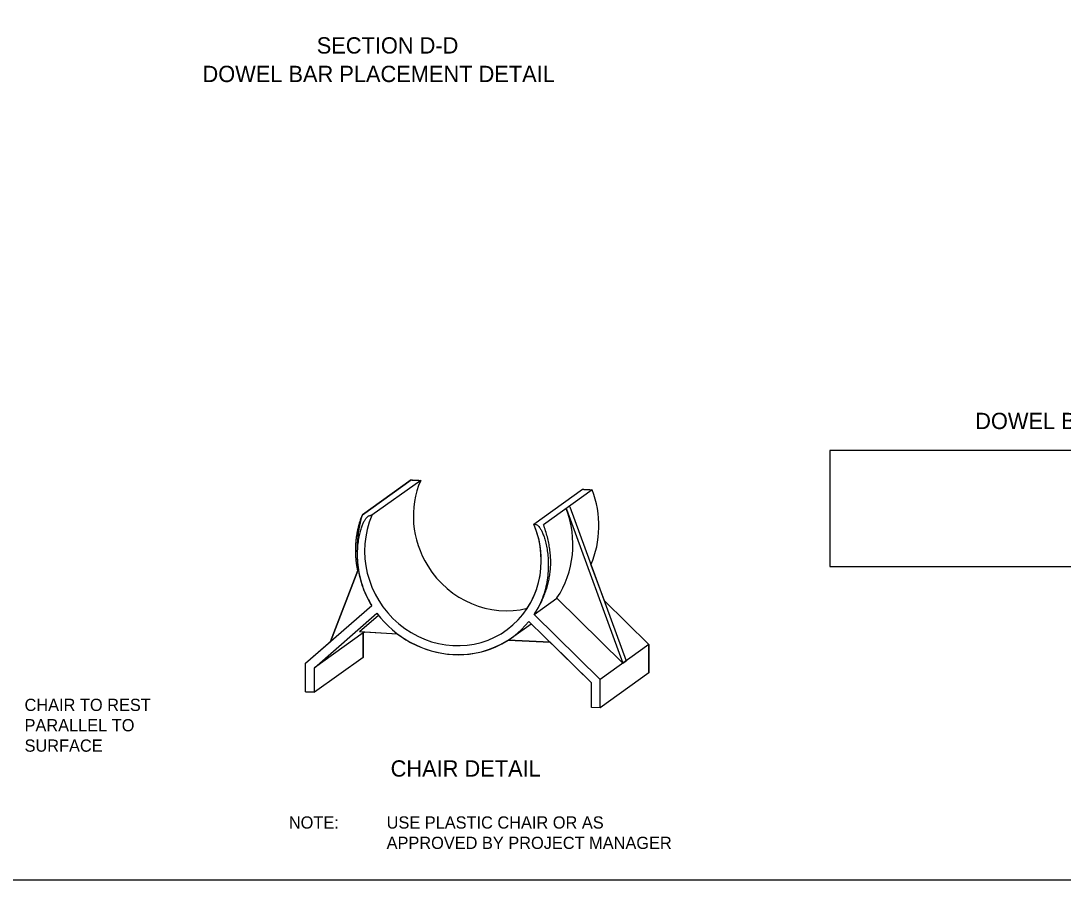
# Model space of a CAD drawing. Extents: x 49991.4 to 50021, y 49987.6 to 50011.4.
# Drawn here: x 50005.98 to 50011.1, y 49987.8 to 49992.02 of the extents above; entities that cross this region are included whole.
import ezdxf

# ---------------------------------------------------------------- set-up
doc = ezdxf.new("R2010")
doc.units = 0
for name, color, linetype in [('Level 1', 7, 'Continuous'), ('Level 15', 7, 'Continuous'), ('Level 16', 7, 'Continuous'), ('Level 2', 7, 'Continuous')]:
    doc.layers.add(name, color=color, linetype=linetype)

msp = doc.modelspace()

# ---------------------------------------------------------------- linework, layer by layer
at = {"layer": 'Level 1'}
for p, q in [((50007.9466, 49989.7609), (50007.7071, 49989.5897)), ((50008.7886, 49989.715), (50008.5492, 49989.5438)), ((50008.6624, 49989.6197), (50008.9394, 49988.8643)), ((50008.6784, 49989.6312), (50008.9554, 49988.8757)), ((50008.5032, 49989.103), (50008.615, 49989.1829)), ((50008.9394, 49988.8643), (50008.615, 49989.1829)), ((50007.3817, 49988.8632), (50007.7062, 49989.1464)), ((50007.4251, 49988.8413), (50007.7318, 49989.1091)), ((50007.7399, 49989.0986), (50007.6468, 49989.0172)), ((50008.3926, 49988.9889), (50008.4887, 49989.0576)), ((50008.7843, 49988.7673), (50008.4776, 49989.0685)), ((50008.8277, 49988.7844), (50008.5032, 49989.103)), ((50007.6646, 49989.0126), (50007.4251, 49988.8413)), ((50007.8335, 49989.007), (50007.6468, 49989.0172)), ((50009.0671, 49988.9556), (50008.8277, 49988.7844)), ((50007.4251, 49988.721), (50007.4251, 49988.8413)), ((50008.8277, 49988.6446), (50008.8277, 49988.7844))]:
    msp.add_line(p, q, dxfattribs=at)
msp.add_lwpolyline([(49999.3835, 49998.9992), (50016.7501, 49998.9992), (50016.7501, 49987.7988), (49999.3835, 49987.7988)], close=True, dxfattribs=at)
for points in [[(50007.6602, 49989.5922), (50007.8997, 49989.7634)], [(50008.5023, 49989.5464), (50008.7417, 49989.7176)], [(50007.8335, 49989.007), (50007.6685, 49989.016), (50007.6646, 49989.0126), (50007.6646, 49988.8922), (50007.4251, 49988.721), (50007.3817, 49988.7234), (50007.3817, 49988.8632), (50007.5036, 49988.9696), (50007.6373, 49989.3195)], [(50008.7825, 49989.3472), (50008.8467, 49989.1721), (50009.0671, 49988.9556), (50009.0671, 49988.8158), (50008.8277, 49988.6446), (50008.7843, 49988.647), (50008.7843, 49988.7673), (50008.5816, 49988.9663), (50008.3759, 49988.9775)]]:
    msp.add_lwpolyline(points, dxfattribs=at)
for centre, major_axis, start_param, end_param in [((50008.3441, 49989.5628), (0.2617, -0.366), 3.653116, 4.644013), ((50008.3441, 49989.5628), (0.2879, -0.4027), 0.51692, 1.295209), ((50008.2164, 49989.4715), (-0.2879, 0.4027), 3.485253, 4.436802), ((50008.1047, 49989.3916), (-0.2617, 0.366), 0.511524, 4.47615), ((50008.1047, 49989.3916), (-0.2617, 0.366), 3.495016, 4.47615), ((50008.3441, 49989.5628), (0.2617, -0.366), 4.644013, 5.929762), ((50008.1047, 49989.3916), (-0.2879, 0.4027), 1.596779, 3.390895), ((50008.1047, 49989.3916), (-0.2879, 0.4027), 1.88936, 3.098314)]:
    msp.add_ellipse(centre, major_axis=major_axis, ratio=0.944998, start_param=start_param, end_param=end_param, dxfattribs=at)
for points, degree in [([(50007.8997, 49989.7634), (50007.9231, 49989.7622), (50007.9466, 49989.7609)], 2), ([(50008.7417, 49989.7176), (50008.7652, 49989.7163), (50008.7886, 49989.715)], 2), ([(50007.6297, 49989.4632), (50007.6359, 49989.5304), (50007.6602, 49989.5922)], 2), ([(50007.7062, 49989.1464), (50007.5705, 49989.3634), (50007.6602, 49989.5922), (50007.6837, 49989.5909), (50007.7071, 49989.5897)], 4), ([(50008.5023, 49989.5464), (50008.5257, 49989.5451), (50008.5492, 49989.5438), (50008.6389, 49989.3052), (50008.5032, 49989.103)], 4), ([(50007.6373, 49989.3195), (50007.6229, 49989.3914), (50007.6297, 49989.4632)], 2)]:
    msp.add_open_spline(points, degree=degree, dxfattribs=at)
at = {"layer": 'Level 15'}
msp.add_line((50008.9394, 49988.8643), (50008.9554, 49988.8757), dxfattribs=at)
at = {"layer": 'Level 16'}
for p, q in [((50007.8997, 49989.7634), (50007.6602, 49989.5922)), ((50008.5023, 49989.5464), (50008.7417, 49989.7176)), ((50007.6373, 49989.3195), (50007.5036, 49988.9696)), ((50009.0671, 49988.9556), (50008.8467, 49989.1721)), ((50007.6646, 49989.0126), (50007.6685, 49989.016)), ((50007.6646, 49988.8922), (50007.6646, 49989.0126)), ((50008.3759, 49988.9775), (50008.5816, 49988.9663)), ((50009.0671, 49988.8158), (50009.0671, 49988.9556)), ((50007.3817, 49988.7234), (50007.3817, 49988.8632)), ((50007.6646, 49988.8922), (50007.4251, 49988.721)), ((50009.0671, 49988.8158), (50008.8277, 49988.6446)), ((50008.7843, 49988.647), (50008.7843, 49988.7673)), ((50007.3817, 49988.7234), (50007.4251, 49988.721)), ((50008.8277, 49988.6446), (50008.7843, 49988.647))]:
    msp.add_line(p, q, dxfattribs=at)
for centre, major_axis, start_param, end_param in [((50008.3441, 49989.5628), (0.2617, -0.366), 3.653116, 4.644013), ((50008.3441, 49989.5628), (0.2879, -0.4027), 0.51692, 1.295209), ((50008.2324, 49989.4829), (-0.2879, 0.4027), 4.428217, 4.436802), ((50008.3441, 49989.5628), (0.2617, -0.366), 4.644013, 5.929762), ((50008.2164, 49989.4715), (-0.2879, 0.4027), 3.482403, 3.485253)]:
    msp.add_ellipse(centre, major_axis=major_axis, ratio=0.944998, start_param=start_param, end_param=end_param, dxfattribs=at)
for points, degree in [([(50007.8997, 49989.7634), (50007.8997, 49989.7634), (50007.8997, 49989.7634), (50007.9231, 49989.7622), (50007.9466, 49989.7609)], 4), ([(50008.7417, 49989.7176), (50008.7652, 49989.7163), (50008.7886, 49989.715)], 2), ([(50007.6602, 49989.5922), (50007.6602, 49989.5922), (50007.6602, 49989.5922), (50007.5705, 49989.3634), (50007.7062, 49989.1464)], 4), ([(50008.5032, 49989.103), (50008.6389, 49989.3052), (50008.5492, 49989.5438)], 2)]:
    msp.add_open_spline(points, degree=degree, dxfattribs=at)
at = {"layer": 'Level 2'}
msp.add_lwpolyline([(50009.9559, 49989.3382), (50013.2227, 49989.3382), (50013.2227, 49989.9081), (50009.9559, 49989.9081)], close=True, dxfattribs=at)

# ---------------------------------------------------------------- texts
for s, height, p in [('SECTION D-D', 0.08, (50007.4362, 49991.8566)), ('DOWEL BAR PLACEMENT DETAIL', 0.08, (50006.8754, 49991.7166)), ('DOWEL BAR DIMENSION TABLE', 0.08, (50010.6689, 49990.0131)), ('CHAIR TO REST ', 0.06, (50006.0017, 49988.6293)), ('PARALLEL TO', 0.06, (50006.0017, 49988.5293)), ('SURFACE', 0.06, (50006.0017, 49988.4293)), ('CHAIR DETAIL', 0.08, (50007.799, 49988.307)), ('NOTE: ', 0.06, (50007.2992, 49988.0519)), ('USE PLASTIC CHAIR OR AS', 0.06, (50007.7792, 49988.0519)), ('APPROVED BY PROJECT MANAGER', 0.06, (50007.7792, 49987.9519))]:
    msp.add_text(s, height=height, dxfattribs=at).set_placement(p)

doc.saveas('drawing.dxf')
